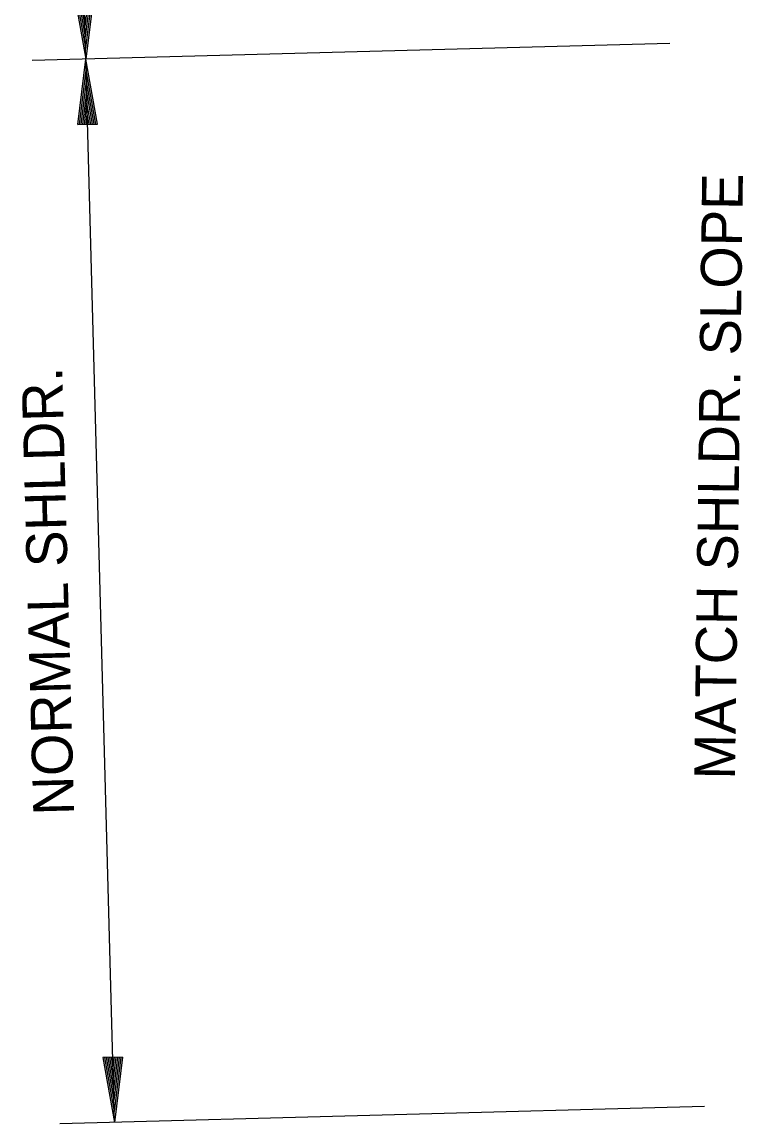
# Model space of a CAD drawing. Extents: x 1929624 to 1936506, y 596315 to 605721.
# Drawn here: x 1932254.7 to 1932360.8, y 600448.6 to 600610.8 of the extents above; entities that cross this region are included whole.
import ezdxf

# ---------------------------------------------------------------- set-up
doc = ezdxf.new("R2010")
doc.units = 0
doc.layers.add('Default', color=7, linetype='Continuous')
doc.layers.add('R_Draft', color=7, linetype='Continuous')

msp = doc.modelspace()

# ---------------------------------------------------------------- linework, layer by layer
at = {"layer": 'Default'}
for p, q in [((1932264.1, 600605.33), (1932262.93, 600649.04)), ((1932262.4, 600614.89), (1932264.1, 600605.33)), ((1932262.64, 600614.89), (1932264.06, 600606.94)), ((1932262.88, 600614.9), (1932264.01, 600608.59)), ((1932263.12, 600614.91), (1932263.97, 600610.18)), ((1932264.56, 600614.95), (1932263.97, 600610.18)), ((1932264.8, 600614.95), (1932264.01, 600608.59)), ((1932265.04, 600614.96), (1932264.06, 600606.94)), ((1932265.28, 600614.97), (1932264.1, 600605.33)), ((1932350.01, 600607.64), (1932256.18, 600605.12)), ((1932262.92, 600595.7), (1932264.1, 600605.33)), ((1932262.92, 600595.7), (1932264.1, 600605.33)), ((1932268.3, 600448.86), (1932264.1, 600605.33)), ((1932265.8, 600595.77), (1932264.1, 600605.33)), ((1932265.8, 600595.77), (1932264.1, 600605.33)), ((1932264.13, 600604.18), (1932264.21, 600601.06)), ((1932263.16, 600595.7), (1932264.14, 600603.72)), ((1932263.16, 600595.7), (1932264.14, 600603.72)), ((1932265.56, 600595.77), (1932264.14, 600603.72)), ((1932265.56, 600595.77), (1932264.14, 600603.72)), ((1932263.4, 600595.71), (1932264.19, 600602.07)), ((1932263.4, 600595.71), (1932264.19, 600602.07)), ((1932265.32, 600595.76), (1932264.19, 600602.07)), ((1932265.32, 600595.76), (1932264.19, 600602.07)), ((1932263.64, 600595.71), (1932264.23, 600600.48)), ((1932263.64, 600595.71), (1932264.23, 600600.48)), ((1932265.08, 600595.75), (1932264.23, 600600.48)), ((1932265.08, 600595.75), (1932264.23, 600600.48)), ((1932263.9, 600595.72), (1932264.27, 600598.85)), ((1932263.9, 600595.72), (1932264.27, 600598.85)), ((1932264.84, 600595.75), (1932264.27, 600598.85)), ((1932264.84, 600595.75), (1932264.27, 600598.85)), ((1932262.92, 600595.7), (1932265.8, 600595.77)), ((1932262.92, 600595.7), (1932265.8, 600595.77)), ((1932264.14, 600595.73), (1932264.32, 600597.25)), ((1932264.14, 600595.73), (1932264.32, 600597.25)), ((1932264.57, 600595.74), (1932264.32, 600597.25)), ((1932264.57, 600595.74), (1932264.32, 600597.25)), ((1932269.48, 600458.49), (1932266.6, 600458.42)), ((1932266.6, 600458.42), (1932268.3, 600448.86)), ((1932266.84, 600458.42), (1932268.26, 600450.47)), ((1932267.08, 600458.43), (1932268.21, 600452.12)), ((1932267.32, 600458.44), (1932268.17, 600453.7)), ((1932267.56, 600458.44), (1932268.13, 600455.34)), ((1932267.83, 600458.45), (1932268.08, 600456.94)), ((1932268.26, 600458.46), (1932268.08, 600456.94)), ((1932268.5, 600458.47), (1932268.13, 600455.34)), ((1932268.76, 600458.47), (1932268.17, 600453.7)), ((1932269, 600458.48), (1932268.21, 600452.12)), ((1932269.24, 600458.49), (1932268.26, 600450.47)), ((1932269.48, 600458.49), (1932268.3, 600448.86)), ((1932355.1, 600451.19), (1932260.26, 600448.64))]:
    msp.add_line(p, q, dxfattribs=at)

# ---------------------------------------------------------------- texts
at = {"layer": 'R_Draft'}
for s, rotation, p in [('MATCH SHLDR. SLOPE', 89.2467, (1932359.61, 600499.3)), ('NORMAL SHLDR.', 91.5377, (1932262.38, 600494.13))]:
    msp.add_text(s, height=6, rotation=rotation, dxfattribs=at).set_placement(p)

doc.saveas('drawing.dxf')
